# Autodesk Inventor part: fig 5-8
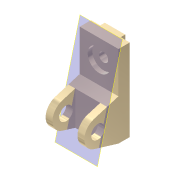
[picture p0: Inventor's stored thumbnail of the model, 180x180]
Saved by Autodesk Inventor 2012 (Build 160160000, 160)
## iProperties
Shininess: 65.0
Angle Display Precision: 2
Document Length Units: 11269
Document Angle Units: 11279
Document Time Units: 11290
Document Mass Units: 11283
Document Length Units Precision: 3
Document Angle Units Precision: 2
Compacted: False
Created: 2001-11
Part Number: fig 5-8
Document SubType Name: Modeling
Designer: Renu Muthoo
Density: 1 g/cm^3
Material: Default
Density: 0.0
Volumn: 0.0
Area: 0.0
PropertySet Name: Model Information
Control State: 0
Master: False
Checked Out: False
Author: Renu Muthoo
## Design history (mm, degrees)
node "Sketch1"
sketch "Sketch2"
  geometry: L1 (33.257, 104.664)-(33.257, -75.336); L2 (33.257, -75.336)-(8.257, -75.336); L3 (8.257, -75.336)-(-45.451, -59.045); L4 (-45.451, -1.628)-(8.257, 14.664); L5 (8.257, 14.664)-(8.257, 104.664); L6 (8.257, 104.664)-(33.257, 104.664); C1 r 15 at (-36.743, -30.336); A1 r 30 centre (-36.743, -30.336) between (-45.451, -1.628) and (-45.451, -59.045)
  constraints: 12 end point, 2 centre point, 2 equal length, 2 parallel, 2 point on circle, 2 tangent, 1 coincident, 1 perpendicular, 1 vertical
  dimensions: "d0" = 180 distance of L1.start L1.end; "d1" = 30 radius of A1; "d2" = 25 distance of L5.end L1.start; "d3" = 45 distance from line of L2 A1.centre; "d4" = 70 distance from line of L1 A1.centre; "d5" = 30 diameter of C1
extrude "Extrusion1" new body sketch "Sketch2" distance "d6" = 85; taper "d7" = 0 deg
workplane "Work Plane1"
sketch "Sketch3"
  geometry: L1 (15, 62.364)-(70, 62.364); L2 (70, 62.364)-(70, -52.386); L3 (70, -52.386)-(15, -52.386); L4 (15, -52.386)-(15, 62.364); L5 (0, -45)-(0, -28.708) reference
  constraints: 8 end point, 2 parallel, 1 horizontal, 1 perpendicular
  dimensions: "d8" = 55 distance of L1.start L1.end; "d9" = 15 distance between parallel lines of L5 L4
extrude "Extrusion2" cut sketch "Sketch3" distance "d10" = 50; taper "d11" = 0 deg
sketch "Sketch4"
  geometry: L1 (0, 25)-(85, 25) reference; L2 (0, 0)-(0, 25) reference; L3 (20, 25)-(65, 25); L4 (65, 25)-(65, 35); L5 (65, 35)-(20, 35); L6 (20, 35)-(20, 25)
  constraints: 8 end point, 2 parallel, 1 horizontal, 1 perpendicular, 1 point on line
  dimensions: "d12" = 45 distance of L4.end L5.end; "d13" = 10 distance of L3.end L4.end; "d14" = 20 distance between parallel lines of L2 L6
extrude "Extrusion3" join sketch "Sketch4" stored distance "d15" = 50; taper "d16" = 0 deg
sketch "Sketch5"
  geometry: L1 (85, 0)-(85, 90) reference; L2 (0, 90)-(85, 90) reference; 1 further point
  dimensions: "d17" = 42 distance from line of L2 point (42.5, 48); "d18" = 42.5 distance from line of L1 point (42.5, 48)
hole "Hole1" sketch "Sketch5" at (42.5, 48) diameter "d19" = 20; stored, may be unused: countersink angle "d23" = 82 deg, drill point angle "d25" = 118 deg; dims "d20" = 6, "d21" = 50, "d22" = 10, "d24" = 8
workplane "Work Plane5"
body "Solid1"
